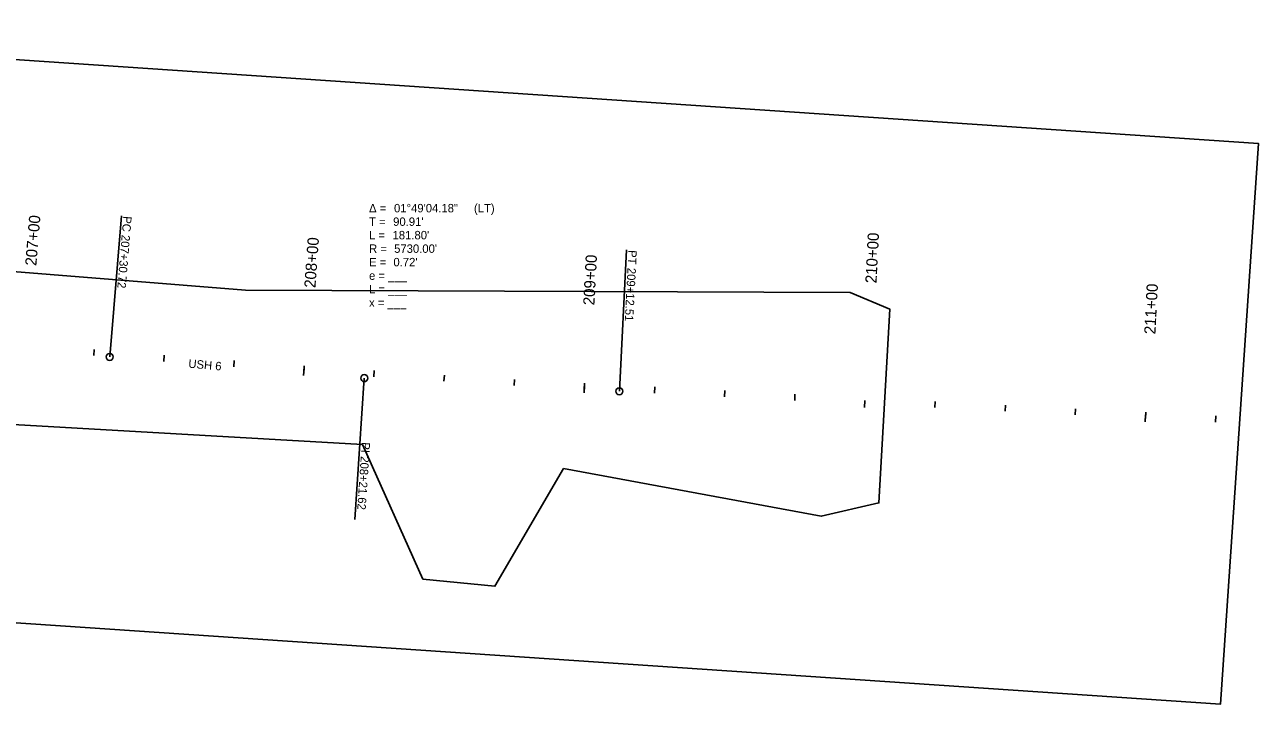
# Model space of a CAD drawing. Extents: x 20499876 to 20505320, y 7953544 to 7954108.
# Drawn here: x 20504399.3 to 20504838.4, y 7953543.8 to 7953785.6 of the extents above; entities that cross this region are included whole.
import ezdxf

# ---------------------------------------------------------------- set-up
doc = ezdxf.new("R2010")
doc.units = 0
for name, color, linetype in [('Draft_0', 7, 'Continuous'), ('Draft_7', 7, 'Continuous'), ('Drainage- Pipe', 7, 'Continuous'), ('PS_CONST', 7, 'Continuous'), ('Revetment', 7, 'Continuous'), ('Wall', 7, 'Continuous')]:
    doc.layers.add(name, color=color, linetype=linetype)

msp = doc.modelspace()

# ---------------------------------------------------------------- linework, layer by layer
at = {"layer": 'Draft_7'}
for p, q in [((20504423.9, 7953667.9), (20504424.08, 7953670.08)), ((20504448.82, 7953665.85), (20504448.99, 7953668.03)), ((20504473.74, 7953663.91), (20504473.91, 7953666.09)), ((20504498.76, 7953663.3), (20504498.59, 7953660.86)), ((20504523.62, 7953660.36), (20504523.76, 7953662.54)), ((20504548.56, 7953658.75), (20504548.7, 7953660.93)), ((20504573.52, 7953657.24), (20504573.65, 7953659.42)), ((20504598.55, 7953657.07), (20504598.41, 7953654.62)), ((20504623.45, 7953654.54), (20504623.56, 7953656.72)), ((20504648.41, 7953653.26), (20504648.52, 7953655.44)), ((20504673.38, 7953651.97), (20504673.49, 7953654.15)), ((20504698.41, 7953651.9), (20504698.28, 7953649.46)), ((20504723.31, 7953649.39), (20504723.43, 7953651.58)), ((20504748.28, 7953648.11), (20504748.39, 7953650.29)), ((20504773.25, 7953646.82), (20504773.36, 7953649)), ((20504798.28, 7953646.76), (20504798.15, 7953644.31)), ((20504823.18, 7953644.25), (20504823.29, 7953646.43))]:
    msp.add_line(p, q, dxfattribs=at)
at = {"layer": 'Drainage- Pipe'}
msp.add_lwpolyline([(20504212.89, 7953785.63), (20504199.4, 7953586.08), (20504824.91, 7953543.82), (20504838.4, 7953743.37)], close=True, dxfattribs=at)
at = {"layer": 'PS_CONST'}
for p, q in [((20504498.68, 7953662.08), (20504498.83, 7953664.26)), ((20504598.48, 7953655.84), (20504598.6, 7953658.03)), ((20504698.41, 7953651.9), (20504698.28, 7953649.46)), ((20504798.21, 7953645.53), (20504798.33, 7953647.71))]:
    msp.add_line(p, q, dxfattribs=at)
at = {"layer": 'Revetment'}
for p, q in [((20504429.6, 7953667.42), (20504433.79, 7953717.65)), ((20504433.79, 7953717.65), (20504433.79, 7953717.65)), ((20504610.98, 7953655.19), (20504613.57, 7953705.52)), ((20504613.57, 7953705.52), (20504613.57, 7953705.52)), ((20504520.19, 7953659.87), (20504516.8, 7953609.58)), ((20504516.8, 7953609.58), (20504516.8, 7953609.58))]:
    msp.add_line(p, q, dxfattribs=at)
for centre in [(20504429.6, 7953667.42), (20504520.19, 7953659.87), (20504610.98, 7953655.19)]:
    msp.add_circle(centre, 1.25, dxfattribs=at)
at = {"layer": 'Wall'}
msp.add_lwpolyline([(20503829.09, 7953744.97), (20504079.02, 7953722.08), (20504247.03, 7953709.66), (20504477.95, 7953691.2), (20504693.1, 7953690.35), (20504707.3, 7953684.41), (20504703.39, 7953615.5), (20504682.83, 7953610.75), (20504591.14, 7953627.72), (20504566.72, 7953585.85), (20504541.05, 7953588.36), (20504519.52, 7953636.21), (20504351.61, 7953645.9), (20504212.21, 7953659.14), (20503994.1, 7953676.75), (20503832.88, 7953690.55)], dxfattribs=at)

# ---------------------------------------------------------------- texts
at = {"layer": 'Draft_0'}
msp.add_text('USH 6', height=3, rotation=355, dxfattribs=at).set_placement((20504457.5, 7953663.61))
at = {"layer": 'Draft_7'}
for s, rotation, p in [('207+00', 85.2308, (20504403.48, 7953699.71)), ('208+00', 85.9236, (20504502.81, 7953691.86)), ('210+00', 87.0487, (20504702.5, 7953693.53)), ('209+00', 86.9235, (20504602.09, 7953685.69)), ('211+00', 87.0487, (20504801.76, 7953675.39))]:
    msp.add_text(s, height=4.008, rotation=rotation, dxfattribs=at).set_placement(p)
at = {"layer": 'Revetment'}
for s, p in [(' (LT)', (20504558.13, 7953718.85)), ('Δ = ', (20504521.9, 7953718.85)), ('01°49\'04.18"', (20504530.79, 7953718.85)), ('T = ', (20504521.9, 7953714.05)), ("90.91'", (20504530.48, 7953714.05)), ('L = ', (20504521.9, 7953709.25)), ("181.80'", (20504530.26, 7953709.25)), ('R = ', (20504521.9, 7953704.45)), ("5730.00'", (20504530.83, 7953704.45)), ('E = ', (20504521.9, 7953699.65)), ("0.72'", (20504530.57, 7953699.65)), ('e = ___ ', (20504521.9, 7953694.85)), ('L = ___', (20504521.9, 7953690.05)), ('x = ___', (20504521.9, 7953685.25))]:
    msp.add_text(s, height=3, dxfattribs=at).set_placement(p)
for s, rotation, p in [('PC', 265.2308, (20504434.45, 7953717.6)), ('207+30.72', 265.2308, (20504433.89, 7953710.95)), ('PT', 267.0487, (20504614.23, 7953705.49)), ('209+12.51', 267.0487, (20504613.9, 7953699.19)), ('PI ', 266.1397, (20504519.32, 7953637.16)), ('208+21.62', 266.1397, (20504518.98, 7953632.16))]:
    msp.add_text(s, height=3, rotation=rotation, dxfattribs=at).set_placement(p)

doc.saveas('drawing.dxf')
